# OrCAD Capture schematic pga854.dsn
size B
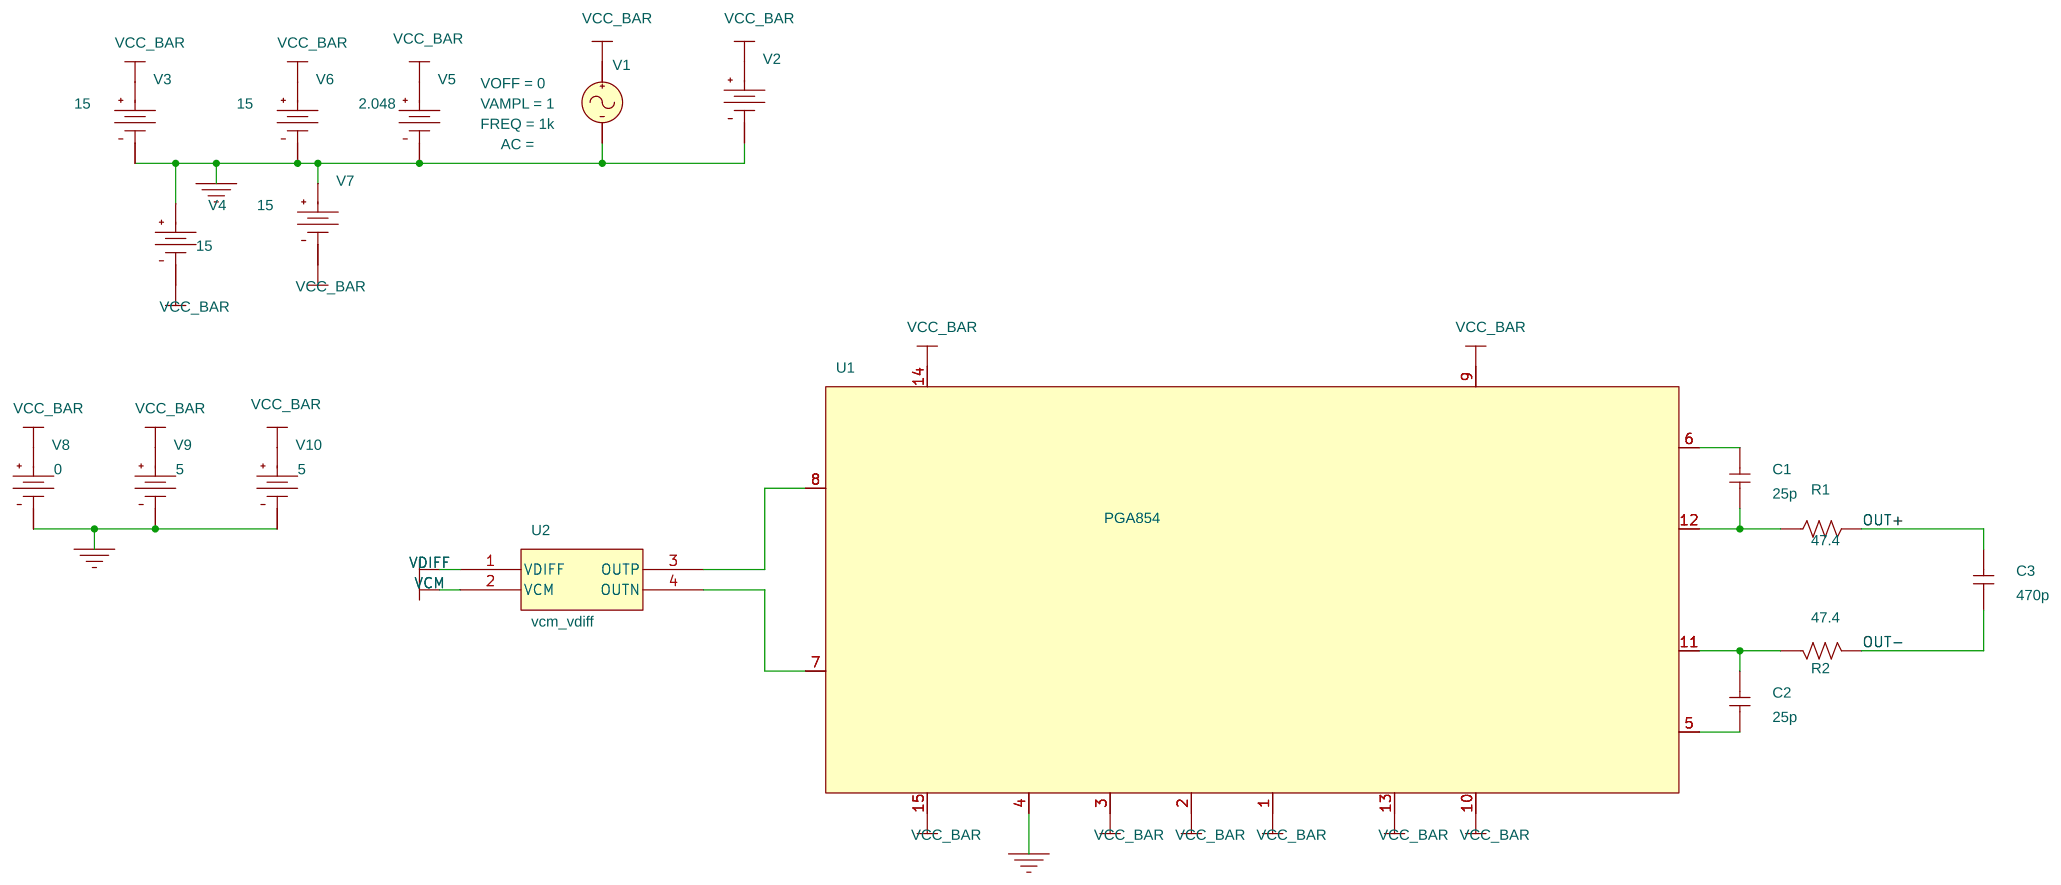
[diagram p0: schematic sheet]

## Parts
C1  25p  [cap196]
C2  25p  [cap196]
C3  470p  [cap196]
R1  47.4  [AXRC05]
R2  47.4  [AXRC05]
U1  PGA854
U2  vcm_vdiff
V1  VSIN
V2  VDC
V3  VDC
V4  VDC
V5  VDC
V6  VDC
V7  VDC
V8  VDC
V9  VDC
V10  VDC

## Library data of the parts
C1-C3 = C
R1 R2 = R
U1 = PGA854
U2 = vcm_vdiff
V1 = VSIN: FREQ: 1k; VAMPL: 1; VOFF: 0
V2 = VDC
V3 V4 V6 V7 = VDC: DC: 15
V5 = VDC: DC: 2.048
V8 = VDC: DC: 0
V9 V10 = VDC: DC: 5

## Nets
Vcc: U1.14(VS+) V3.0(+)
Vee: U1.15(VS-) V4.1(-)
0: U1.4(DGND) V1.2(-) V2.1(-) V3.1(-) V4.0(+) V5.1(-) V6.1(-) V7.0(+) V8.1(-) V9.1(-) V10.1(-)
A0: U1.1(A0) V10.0(+)
A1: U1.2(A1) V9.0(+)
A2: U1.3(A2) V8.0(+)
LVDD: U1.9(LVDD) V6.0(+)
LVSS: U1.10(LVSS) V7.1(-)
OUT+: C3.2 R1.2
OUT-: C3.1 R2.2
VCM: U2.2(VCM) V2.0(+)
Vdiff: U2.1(VDIFF) V1.1(+)
VOCM: U1.13(VOCM) V5.0(+)
N00144: U1.8(INP) U2.3(OUTP)
N00152: U1.7(INN) U2.4(OUTN)
N00399: C2.1 U1.5(FDA_IN+)
N00403: C1.2 U1.6(FDA_IN-)
N00469: C2.2 R2.1 U1.11(OUTN)
N00476: C1.1 R1.1 U1.12(OUTP)
